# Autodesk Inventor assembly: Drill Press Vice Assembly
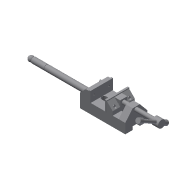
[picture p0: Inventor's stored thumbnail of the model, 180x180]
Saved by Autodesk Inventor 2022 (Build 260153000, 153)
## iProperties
Created: 2011-07
Part Number: Drill Press Vice Assembly
Document SubType Name: Assembly
Designer: CadCim
Author: CadCim
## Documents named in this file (9)
- D:\PROJECTS_2021\Resources\Tutorial Files\c13_Inv_2022_tut\c13_Inv_tut_2022\c13-tut02-inv\Drill Press vice\Drill Press Vice\Drill Press Vice Assembly.iam
- D:\PROJECTS_2021\Resources\Tutorial Files\c13_Inv_2022_tut\c13_Inv_tut_2022\c13-tut02-inv\Drill Press vice\Drill Press Vice\Base.ipt
- D:\PROJECTS_2021\Resources\Tutorial Files\c13_Inv_2022_tut\c13_Inv_tut_2022\c13-tut02-inv\Drill Press vice\Drill Press Vice\Jaw Face.ipt
- D:\PROJECTS_2021\Resources\Tutorial Files\c13_Inv_2022_tut\c13_Inv_tut_2022\c13-tut02-inv\Drill Press vice\Drill Press Vice\Movable Jaw.ipt
- D:\PROJECTS_2021\Resources\Tutorial Files\c13_Inv_2022_tut\c13_Inv_tut_2022\c13-tut02-inv\Drill Press vice\Drill Press Vice\Safety Handle.ipt
- D:\PROJECTS_2021\Resources\Tutorial Files\c13_Inv_2022_tut\c13_Inv_tut_2022\c13-tut02-inv\Drill Press vice\Drill Press Vice\Clamp Screw.ipt
- D:\PROJECTS_2021\Resources\Tutorial Files\c13_Inv_2022_tut\c13_Inv_tut_2022\c13-tut02-inv\Drill Press vice\Drill Press Vice\Clamp Screw Handle.ipt
- D:\PROJECTS_2021\Resources\Tutorial Files\c13_Inv_2022_tut\c13_Inv_tut_2022\c13-tut02-inv\Drill Press vice\Drill Press Vice\Handle Stop.ipt
- D:\PROJECTS_2021\Resources\Tutorial Files\c13_Inv_2022_tut\c13_Inv_tut_2022\c13-tut02-inv\Drill Press vice\Drill Press Vice\Cap Screw.ipt
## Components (13 placed, 8 different names)
1. Base:1 — Insert:3, Insert:9, Insert:10, Mate:8, Mate:9, Mate:12, Mate:13
2. Jaw Face:1 — Mate:10, Mate:11, Mate:12
3. Movable Jaw:1 — Mate:3, Insert:4, Insert:11, Insert:12, Mate:9, Mate:13, Mate:15
4. Safety Handle:1 — Insert:3
5. Clamp Screw:1 — Mate:3, Insert:4, Mate:4, Mate:6, Mate:8
6. Clamp Screw Handle:1 — Mate:4, Insert:7, Insert:8
7. Jaw Face:2 — Mate:14, Mate:15
8. Handle Stop:1 — Insert:7, Mate:6
9. Handle Stop:2 — Insert:8
10. Cap Screw:1 — Insert:12
11. Cap Screw:2 — Insert:11, Mate:14
12. Cap Screw:3 — Insert:10, Mate:11
13. Cap Screw:4 — Insert:9, Mate:10
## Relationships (19: Mate 11, Insert 8)
- Insert:3: Base:1 ↔ Safety Handle:1
- Mate:3: Movable Jaw:1 ↔ Clamp Screw:1
- Insert:4: Movable Jaw:1 ↔ Clamp Screw:1
- Mate:4: Clamp Screw:1 ↔ Clamp Screw Handle:1
- Insert:7: Clamp Screw Handle:1 ↔ Handle Stop:1
- Insert:8: Clamp Screw Handle:1 ↔ Handle Stop:2
- Mate:6: Clamp Screw:1 ↔ Handle Stop:1
- Insert:9: Base:1 ↔ Cap Screw:4
- Insert:10: Base:1 ↔ Cap Screw:3
- Insert:11: Movable Jaw:1 ↔ Cap Screw:2
- Insert:12: Movable Jaw:1 ↔ Cap Screw:1
- Mate:8: Base:1 ↔ Clamp Screw:1
- Mate:9: Base:1 ↔ Movable Jaw:1
- Mate:10: Jaw Face:1 ↔ Cap Screw:4
- Mate:11: Jaw Face:1 ↔ Cap Screw:3
- Mate:12: Base:1 ↔ Jaw Face:1
- Mate:13: Base:1 ↔ Movable Jaw:1
- Mate:14: Jaw Face:2 ↔ Cap Screw:2
- Mate:15: Movable Jaw:1 ↔ Jaw Face:2
